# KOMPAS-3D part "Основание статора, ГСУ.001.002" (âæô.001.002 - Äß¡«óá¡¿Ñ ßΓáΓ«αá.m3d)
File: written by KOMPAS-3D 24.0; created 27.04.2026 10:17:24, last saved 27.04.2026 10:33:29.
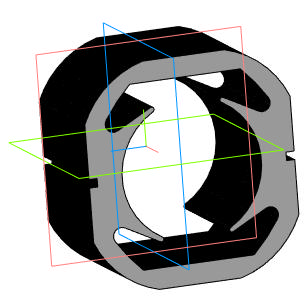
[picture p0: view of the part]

Document properties: Автор: User7; Полное имя файла: C:\Users\User7\Desktop\олимп\ГСУ.001.002 - Основание статора.m3d

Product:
- Part/product: Основание статора  | designation ГСУ.001.002
    Масса: 0.01025

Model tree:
1. Эскиз:1
2. Элемент выдавливания:1
     Расстояние 1 = 0.02
3. Зеркальный массив:1
4. Экземпляр ( 1 )
5. Экземпляр ( 2 )  (with: Элемент выдавливания:1)
6. Зеркальный массив:2  (with: Экземпляр ( 1 ), Экземпляр ( 2 ), Зеркальный массив:1, Элемент выдавливания:1)
7. Эскиз:2  (with: Грань.Элемент выдавливания:1)  (labels: Ребро.Элемент выдавливания:1.Экземпляр ( 1 ); Ребро.Элемент выдавливания:1.Экземпляр ( 2 ))
8. Элемент выдавливания:2
     Расстояние 2 = 10
9. Массив по сетке:1  (with: Зеркальный массив:2, Зеркальный массив:1, Элемент выдавливания:1)  (442 pattern instances)
     Шаг 1 = 0.515625; Угол раствора = 90

Expressions: 34/2; 50.1/2; 36.3/2; 17.2/2; 40.1/2
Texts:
  ГСУ.001.002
